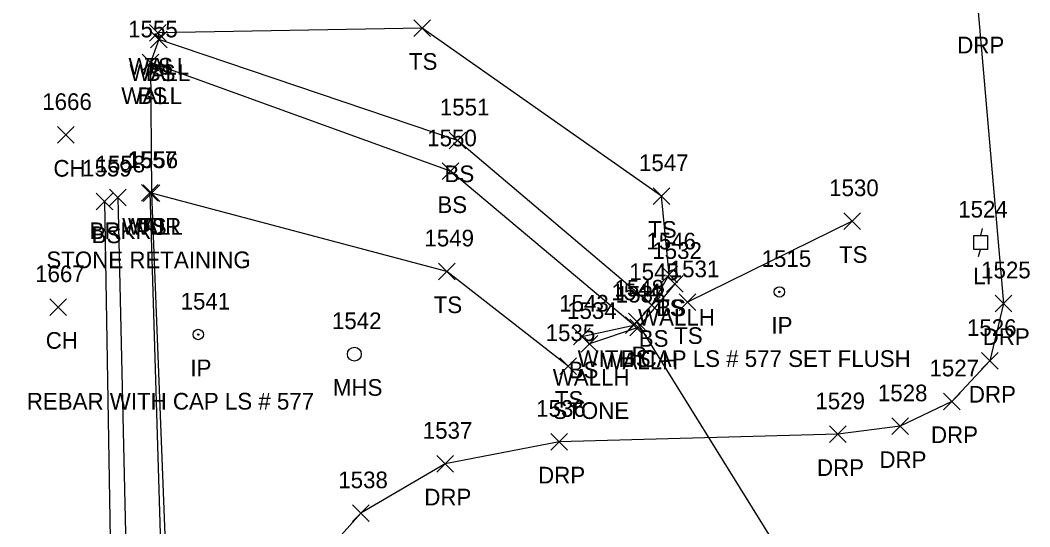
# Model space of a CAD drawing. Extents: x 1651305 to 1654558, y 539481 to 548441.
# Drawn here: x 1654364.2 to 1654485.4, y 544816.8 to 544877.6 of the extents above; entities that cross this region are included whole.
import ezdxf

# ---------------------------------------------------------------- set-up
doc = ezdxf.new("R2010")
doc.units = 0
for name, color, linetype in [('D_A', 7, 'Continuous'), ('D_C', 7, 'Continuous'), ('D_I', 7, 'Continuous'), ('D_TIC', 7, 'Continuous'), ('DCP', 7, 'Continuous'), ('DHW', 7, 'Continuous'), ('L_A', 7, 'Continuous'), ('L_C', 7, 'Continuous'), ('L_I', 7, 'Continuous'), ('L_TIC', 7, 'Continuous'), ('LAWA', 7, 'Continuous'), ('LAWE', 7, 'Continuous'), ('LELB', 7, 'Continuous'), ('LW', 7, 'Continuous'), ('M_A', 7, 'Continuous'), ('M_C', 7, 'Continuous'), ('M_I', 7, 'Continuous'), ('MPIR', 7, 'Continuous'), ('R_A', 7, 'Continuous'), ('R_I', 7, 'Continuous'), ('R_TIC', 7, 'Continuous'), ('RDP', 7, 'Continuous'), ('U_A', 7, 'Continuous'), ('U_I', 7, 'Continuous'), ('ULP', 7, 'Continuous'), ('USMH', 7, 'Continuous')]:
    doc.layers.add(name, color=color, linetype=linetype)

msp = doc.modelspace()

# ---------------------------------------------------------------- linework, layer by layer
at = {"layer": 'D_TIC'}
for points in [[(1654441.77, 544844.93), (1654443.77, 544846.93)], [(1654443.77, 544844.93), (1654441.77, 544846.93)], [(1654437.22, 544840.41), (1654439.22, 544842.41)], [(1654439.22, 544840.41), (1654437.22, 544842.41)], [(1654437.37, 544839.7), (1654439.37, 544841.7)], [(1654439.37, 544839.7), (1654437.37, 544841.7)], [(1654431.53, 544837.73), (1654433.53, 544839.73)], [(1654433.53, 544837.73), (1654431.53, 544839.73)]]:
    msp.add_lwpolyline(points, dxfattribs=at)
at = {"layer": 'DCP'}
msp.add_lwpolyline([(1654470.3, 544789.74), (1654438.22, 544841.41)], dxfattribs=at)
at = {"layer": 'DHW'}
msp.add_lwpolyline([(1654442.77, 544845.93), (1654438.37, 544840.7), (1654432.53, 544838.73)], dxfattribs=at)
at = {"layer": 'L_TIC'}
for points in [[(1654411.45, 544875.62), (1654413.45, 544877.62)], [(1654413.45, 544875.62), (1654411.45, 544877.62)], [(1654379.71, 544875.04), (1654381.71, 544877.04)], [(1654381.71, 544875.04), (1654379.71, 544877.04)], [(1654379.71, 544875.04), (1654381.71, 544877.04)], [(1654381.71, 544875.04), (1654379.71, 544877.04)], [(1654379.84, 544874.27), (1654381.84, 544876.27)], [(1654381.84, 544874.27), (1654379.84, 544876.27)], [(1654379.84, 544874.27), (1654381.84, 544876.27)], [(1654381.84, 544874.27), (1654379.84, 544876.27)], [(1654378.86, 544871.51), (1654380.86, 544873.51)], [(1654380.86, 544871.51), (1654378.86, 544873.51)], [(1654378.86, 544871.51), (1654380.86, 544873.51)], [(1654380.86, 544871.51), (1654378.86, 544873.51)], [(1654368.7, 544862.8), (1654370.7, 544864.8)], [(1654370.7, 544862.8), (1654368.7, 544864.8)], [(1654415.69, 544862.14), (1654417.69, 544864.14)], [(1654417.69, 544862.14), (1654415.69, 544864.14)], [(1654414.83, 544858.44), (1654416.83, 544860.44)], [(1654416.83, 544858.44), (1654414.83, 544860.44)], [(1654378.78, 544855.85), (1654380.78, 544857.85)], [(1654380.78, 544855.85), (1654378.78, 544857.85)], [(1654378.95, 544855.82), (1654380.95, 544857.82)], [(1654380.95, 544855.82), (1654378.95, 544857.82)], [(1654378.95, 544855.82), (1654380.95, 544857.82)], [(1654380.95, 544855.82), (1654378.95, 544857.82)], [(1654373.34, 544854.82), (1654375.34, 544856.82)], [(1654375.34, 544854.82), (1654373.34, 544856.82)], [(1654374.94, 544855.31), (1654376.94, 544857.31)], [(1654376.94, 544855.31), (1654374.94, 544857.31)], [(1654440.16, 544855.47), (1654442.16, 544857.47)], [(1654442.16, 544855.47), (1654440.16, 544857.47)], [(1654463.07, 544852.46), (1654465.07, 544854.46)], [(1654465.07, 544852.46), (1654463.07, 544854.46)], [(1654414.42, 544846.43), (1654416.42, 544848.43)], [(1654416.42, 544846.43), (1654414.42, 544848.43)], [(1654441.11, 544846.07), (1654443.11, 544848.07)], [(1654443.11, 544846.07), (1654441.11, 544848.07)], [(1654441.11, 544846.07), (1654443.11, 544848.07)], [(1654443.11, 544846.07), (1654441.11, 544848.07)], [(1654439, 544842.39), (1654441, 544844.39)], [(1654441, 544842.39), (1654439, 544844.39)], [(1654439, 544842.39), (1654441, 544844.39)], [(1654441, 544842.39), (1654439, 544844.39)], [(1654443.29, 544842.73), (1654445.29, 544844.73)], [(1654445.29, 544842.73), (1654443.29, 544844.73)], [(1654367.78, 544842.15), (1654369.78, 544844.15)], [(1654369.78, 544842.15), (1654367.78, 544844.15)], [(1654436.85, 544839.98), (1654438.85, 544841.98)], [(1654438.85, 544839.98), (1654436.85, 544841.98)], [(1654436.85, 544839.98), (1654438.85, 544841.98)], [(1654438.85, 544839.98), (1654436.85, 544841.98)], [(1654430.59, 544838.61), (1654432.59, 544840.61)], [(1654432.59, 544838.61), (1654430.59, 544840.61)], [(1654428.96, 544835.07), (1654430.96, 544837.07)], [(1654430.96, 544835.07), (1654428.96, 544837.07)]]:
    msp.add_lwpolyline(points, dxfattribs=at)
at = {"layer": 'LAWA'}
msp.add_lwpolyline([(1654379.78, 544856.85), (1654381.23, 544808.02), (1654382.76, 544783.06), (1654378, 544758.08), (1654381.89, 544756.13), (1654381.66, 544736.71), (1654380.9, 544705.78), (1654381.56, 544700.36), (1654376.77, 544678.51), (1654368.51, 544665.19)], dxfattribs=at)
at = {"layer": 'LAWE'}
msp.add_lwpolyline([(1654375.94, 544856.31), (1654377.08, 544805.55), (1654378.9, 544780.84), (1654375.25, 544758.97), (1654375.2, 544735.18), (1654374.98, 544710.3), (1654371.32, 544695.81), (1654368.77, 544679.57), (1654363.1, 544667.03), (1654358.05, 544658.63), (1654352.36, 544650.11), (1654344.9, 544634.32), (1654334.88, 544605.42), (1654326.4, 544588.83), (1654321.27, 544565.19), (1654313.3, 544530.3), (1654300.22, 544501.74), (1654283.17, 544465.47), (1654261.06, 544441.26)], dxfattribs=at)
at = {"layer": 'LELB'}
for points in [[(1654442.11, 544847.07), (1654441.16, 544856.47), (1654412.45, 544876.62), (1654380.71, 544876.04)], [(1654440, 544843.39), (1654416.69, 544863.14), (1654380.84, 544875.27)], [(1654437.85, 544840.98), (1654415.83, 544859.44), (1654379.86, 544872.51)], [(1654429.96, 544836.07), (1654415.42, 544847.43), (1654379.95, 544856.82)], [(1654374.34, 544855.82), (1654375.22, 544803.45), (1654375.07, 544780.81), (1654373.47, 544758.47), (1654373.91, 544734.87), (1654373.92, 544712.91), (1654369.62, 544696.27), (1654366.92, 544680.67), (1654362.17, 544668.56), (1654357.64, 544659.43), (1654350.7, 544650.57), (1654343.25, 544636.93), (1654333.62, 544607.27), (1654325.31, 544589.17), (1654319.06, 544565.66), (1654310.74, 544531.11), (1654298.27, 544501.75), (1654282.29, 544466.34), (1654260.01, 544442.91)], [(1654464.07, 544853.46), (1654444.29, 544843.73)], [(1654431.59, 544839.61), (1654437.85, 544840.98), (1654440, 544843.39), (1654442.11, 544847.07)]]:
    msp.add_lwpolyline(points, dxfattribs=at)
at = {"layer": 'LW'}
msp.add_lwpolyline([(1654380.71, 544876.04), (1654380.84, 544875.27), (1654379.86, 544872.51), (1654379.95, 544856.82), (1654381.84, 544808.65), (1654383.25, 544783.57)], dxfattribs=at)
at = {"layer": 'MPIR'}
for centre, radius in [((1654455.32, 544844.97), 0.625), ((1654455.32, 544844.97), 0.0833), ((1654385.58, 544839.86), 0.625), ((1654385.58, 544839.86), 0.0833)]:
    msp.add_circle(centre, radius, dxfattribs=at)
at = {"layer": 'R_TIC'}
for points in [[(1654481.23, 544842.6), (1654483.23, 544844.6)], [(1654483.23, 544842.6), (1654481.23, 544844.6)], [(1654479.57, 544835.69), (1654481.57, 544837.69)], [(1654481.57, 544835.69), (1654479.57, 544837.69)], [(1654475.02, 544830.84), (1654477.02, 544832.84)], [(1654477.02, 544830.84), (1654475.02, 544832.84)], [(1654468.83, 544827.85), (1654470.83, 544829.85)], [(1654470.83, 544827.85), (1654468.83, 544829.85)], [(1654461.34, 544826.89), (1654463.34, 544828.89)], [(1654463.34, 544826.89), (1654461.34, 544828.89)], [(1654427.87, 544825.99), (1654429.87, 544827.99)], [(1654429.87, 544825.99), (1654427.87, 544827.99)], [(1654414.21, 544823.36), (1654416.21, 544825.36)], [(1654416.21, 544823.36), (1654414.21, 544825.36)], [(1654404.08, 544817.42), (1654406.08, 544819.42)], [(1654406.08, 544817.42), (1654404.08, 544819.42)]]:
    msp.add_lwpolyline(points, dxfattribs=at)
at = {"layer": 'RDP'}
msp.add_lwpolyline([(1654473.04, 544948.78), (1654475.1, 544921.55), (1654479.17, 544878.59), (1654482.23, 544843.6), (1654480.57, 544836.69), (1654476.02, 544831.84), (1654469.83, 544828.85), (1654462.34, 544827.89), (1654428.87, 544826.99), (1654415.21, 544824.36), (1654405.08, 544818.42), (1654397.43, 544809.88), (1654392.82, 544795.19), (1654389.4, 544756.56), (1654387.7, 544737.06)], dxfattribs=at)
at = {"layer": 'ULP'}
for p, q in [((1654478.64, 544850.06), (1654478.64, 544851.73)), ((1654478.64, 544851.73), (1654480.31, 544851.73)), ((1654479.64, 544852.56), (1654479.47, 544851.73)), ((1654480.31, 544851.73), (1654480.31, 544850.06)), ((1654479.47, 544850.89), (1654479.47, 544850.89)), ((1654480.31, 544850.06), (1654478.64, 544850.06)), ((1654479.22, 544849.23), (1654479.47, 544850.06))]:
    msp.add_line(p, q, dxfattribs=at)
at = {"layer": 'USMH'}
for p, q in [((1654404.31, 544837.51), (1654404.31, 544837.51)), ((1654405.15, 544837.51), (1654405.15, 544837.51))]:
    msp.add_line(p, q, dxfattribs=at)
msp.add_circle((1654404.31, 544837.51), 0.833, dxfattribs=at)

# ---------------------------------------------------------------- texts
at = {"layer": 'D_A'}
for s, p in [('WALLH', (1654438.36, 544840.93)), ('P', (1654437.59, 544836.41)), ('WALLH', (1654433.96, 544835.7)), ('WALLH', (1654428.12, 544833.73))]:
    msp.add_text(s, height=2, dxfattribs=at).set_placement(p)
at = {"layer": 'D_C'}
msp.add_text('STONE', height=2, dxfattribs=at).set_placement((1654428.08, 544829.73))
at = {"layer": 'D_I'}
for s, p in [('1532', (1654440.07, 544848.93)), ('1548', (1654435.52, 544844.41)), ('1533', (1654435.68, 544843.7)), ('1534', (1654429.84, 544841.73))]:
    msp.add_text(s, height=2, dxfattribs=at).set_placement(p)
at = {"layer": 'L_A'}
for s, p in [('TS', (1654410.86, 544871.62)), ('WALL', (1654377.2, 544871.04)), ('WALL', (1654377.33, 544870.27)), ('TS', (1654379.12, 544871.04)), ('BS', (1654379.28, 544870.27)), ('WALL', (1654376.34, 544867.51)), ('BS', (1654378.3, 544867.51)), ('CH', (1654368.19, 544858.8)), ('BS', (1654415.13, 544858.14)), ('BS', (1654414.27, 544854.44)), ('BRKR', (1654372.53, 544851.31)), ('WALL', (1654376.44, 544851.82)), ('WDR', (1654377.14, 544851.85)), ('TS', (1654378.36, 544851.82)), ('TS', (1654439.57, 544851.47)), ('BS', (1654372.78, 544850.82)), ('TS', (1654462.48, 544848.46)), ('TS', (1654413.83, 544842.43)), ('TS', (1654440.52, 544842.07)), ('BS', (1654440.55, 544842.07)), ('TS', (1654442.69, 544838.73)), ('CH', (1654367.27, 544838.15)), ('BS', (1654438.44, 544838.39)), ('BS', (1654438.44, 544838.39)), ('BS', (1654436.29, 544835.98)), ('BS', (1654436.29, 544835.98)), ('BS', (1654430.03, 544834.61)), ('TS', (1654428.37, 544831.07))]:
    msp.add_text(s, height=2, dxfattribs=at).set_placement(p)
at = {"layer": 'L_C'}
msp.add_text('STONE RETAINING', height=2, dxfattribs=at).set_placement((1654367.35, 544847.82))
at = {"layer": 'L_I'}
for s, p in [('1555', (1654377.16, 544875.51)), ('1555', (1654377.16, 544875.51)), ('1666', (1654366.85, 544866.8)), ('1551', (1654414.57, 544866.14)), ('1550', (1654413.05, 544862.44)), ('1557', (1654377.09, 544859.85)), ('1556', (1654377.21, 544859.82)), ('1556', (1654377.21, 544859.82)), ('1547', (1654438.47, 544859.47)), ('1559', (1654371.64, 544858.82)), ('1558', (1654373.25, 544859.31)), ('1530', (1654461.29, 544856.46)), ('1549', (1654412.72, 544850.43)), ('1546', (1654439.36, 544850.07)), ('1546', (1654439.36, 544850.07)), ('1667', (1654366, 544846.15)), ('1545', (1654437.3, 544846.39)), ('1545', (1654437.3, 544846.39)), ('1531', (1654442.16, 544846.73)), ('1544', (1654435.16, 544843.98)), ('1544', (1654435.16, 544843.98)), ('1543', (1654428.89, 544842.61)), ('1535', (1654427.27, 544839.07))]:
    msp.add_text(s, height=2, dxfattribs=at).set_placement(p)
at = {"layer": 'M_A'}
for p in [(1654454.36, 544839.97), (1654384.63, 544834.86)]:
    msp.add_text('IP', height=2, dxfattribs=at).set_placement(p)
at = {"layer": 'M_C'}
for s, p in [('WITH CAP LS # 577 SET FLUSH', (1654431.1, 544835.97)), ('REBAR WITH CAP LS # 577', (1654365, 544830.86))]:
    msp.add_text(s, height=2, dxfattribs=at).set_placement(p)
at = {"layer": 'M_I'}
for s, p in [('1515', (1654453.19, 544847.97)), ('1541', (1654383.46, 544842.86))]:
    msp.add_text(s, height=2, dxfattribs=at).set_placement(p)
at = {"layer": 'R_A'}
for p in [(1654476.66, 544873.59), (1654479.72, 544838.6), (1654478.06, 544831.69), (1654473.51, 544826.84), (1654467.32, 544823.85), (1654426.36, 544821.99), (1654459.83, 544822.89), (1654412.7, 544819.36)]:
    msp.add_text('DRP', height=2, dxfattribs=at).set_placement(p)
at = {"layer": 'R_I'}
for s, p in [('1525', (1654479.53, 544846.6)), ('1526', (1654477.83, 544839.69)), ('1527', (1654473.33, 544834.84)), ('1528', (1654467.14, 544831.85)), ('1529', (1654459.64, 544830.89)), ('1536', (1654426.13, 544829.99)), ('1537', (1654412.52, 544827.36)), ('1538', (1654402.38, 544821.42))]:
    msp.add_text(s, height=2, dxfattribs=at).set_placement(p)
at = {"layer": 'U_A'}
for s, p in [('LI', (1654478.58, 544845.89)), ('MHS', (1654401.73, 544832.51))]:
    msp.add_text(s, height=2, dxfattribs=at).set_placement(p)
at = {"layer": 'U_I'}
for s, p in [('1524', (1654476.78, 544853.89)), ('1542', (1654401.62, 544840.51))]:
    msp.add_text(s, height=2, dxfattribs=at).set_placement(p)

doc.saveas('drawing.dxf')
